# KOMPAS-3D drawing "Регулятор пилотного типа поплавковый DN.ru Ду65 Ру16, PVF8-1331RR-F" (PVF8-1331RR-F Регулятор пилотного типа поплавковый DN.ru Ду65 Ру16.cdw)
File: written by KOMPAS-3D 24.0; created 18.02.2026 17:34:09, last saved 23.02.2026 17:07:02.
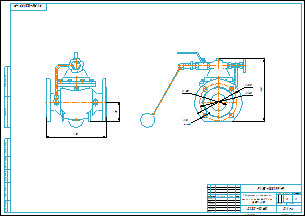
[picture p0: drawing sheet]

Document properties: art: D230-10612; Автор: R2D2; Форматы листов документа: A2; Полное имя файла: PVF8-1331RR-F Регулятор пилотного типа поплавковый DN.ru Ду65 Ру16.m3d; Масса: 10; Наименование: Регулятор пилотного типа поплавковый DN.ru Ду65 Ру16; Количество листов документа: 1; Примечание: D230-10612

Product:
- Part/product: Регулятор пилотного типа поплавковый DN.ru Ду65 Ру16  | designation PVF8-1331RR-F
    Масса: 10
    Раздел спецификации: Прочие изделия
    Примечание: D230-10612
    additional columns: D230-10612

Referenced files in E:\Работа\Зайцев\Для компаса\: чертеж DN.ru А3.cdt
Referenced files in E:\Работа\Зайцев\PVF8-1331RR-F Регулятор пилотного типа поплавковый DN.ru Ду15-300\DN65\: PVF8-1331RR-F Регулятор пилотного типа поплавковый DN.ru Ду65 Ру16.m3d
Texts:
  чертеж DN.ru А3.cdt
  Регулятор пилотного
  типа поплавковый DN.ru
  Ду65 Ру16
  PVF8-1331RR-F
  prop
  Регулятор пилотного типа поплавковый DN.ru Ду65 Ру16
  PVF8-1331RR-F Регулятор пилотного типа поплавковый DN.ru Ду65 Ру16
Dimensions and other numbers on the sheet: 1:2; 0; 1; 2; 10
